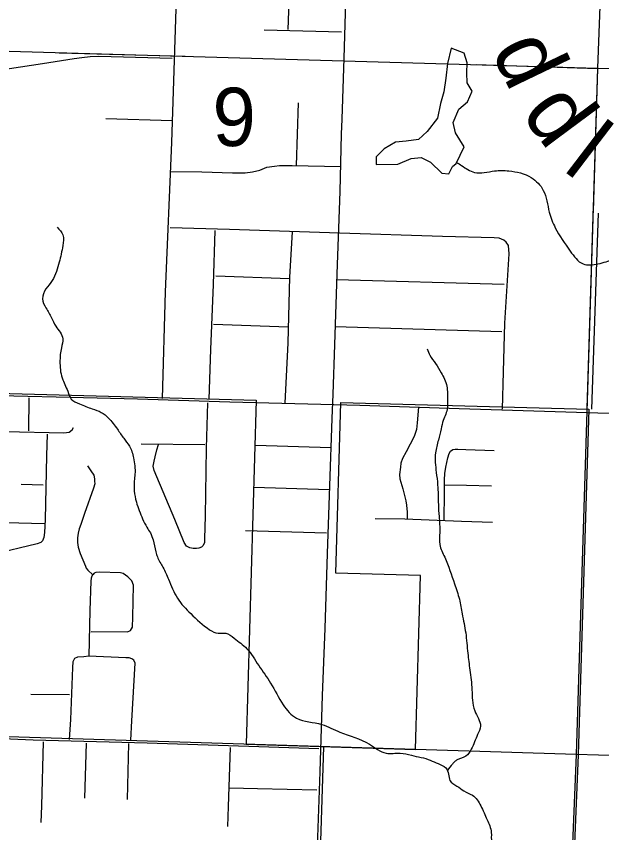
# Model space of a CAD drawing. Extents: x 1219626 to 1426462, y 456797 to 752399.
# Drawn here: x 1322578 to 1327096, y 647254 to 653553 of the extents above; entities that cross this region are included whole.
import ezdxf

# ---------------------------------------------------------------- set-up
doc = ezdxf.new("R2010")
doc.units = 0
for name, color, linetype in [('Cities Incorporated Area', 7, 'Continuous'), ('City Streets', 7, 'Continuous'), ('Connecting Roads', 7, 'Continuous'), ('Lakes and Ponds', 7, 'Continuous'), ('Local Roads Improved', 7, 'Continuous'), ('Local Roads Paved', 7, 'Continuous'), ('Masks', 7, 'Continuous'), ('Narrow River Creek and Branch and Slough', 7, 'Continuous'), ('Narrow River Creek and Branch and Slough Text', 7, 'Continuous'), ('Section Lines', 7, 'Continuous'), ('Section Numbers', 7, 'Continuous')]:
    doc.layers.add(name, color=color, linetype=linetype)

msp = doc.modelspace()

# ---------------------------------------------------------------- linework, layer by layer
at = {"layer": 'Cities Incorporated Area'}
for p, q in [((1319885.5, 650716.4), (1324429, 650591.4)), ((1324429, 650591.4), (1324350.8, 647936.5)), ((1325044.4, 649257.1), (1325083.1, 650573.4)), ((1325083.1, 650573.4), (1326997.1, 650520.9)), ((1326997.1, 650520.9), (1326914.4, 647855.9)), ((1325698.5, 649237.8), (1325044.4, 649257.1)), ((1325659.3, 647895.3), (1325698.5, 649237.8)), ((1324350.8, 647936.5), (1325659.3, 647895.3)), ((1326914.4, 647855.9), (1326816, 645432.8))]:
    msp.add_line(p, q, dxfattribs=at)
at = {"layer": 'City Streets'}
for p, q in [((1322674.9, 650609.4), (1322671.5, 650355.6)), ((1323542.1, 650254.1), (1324034.2, 650249.8)), ((1322785.9, 649934.9), (1322616.4, 649940.1)), ((1322989.8, 648316.6), (1322691.2, 648320)), ((1323116.3, 647944.1), (1323105.1, 647519.9)), ((1323444, 647941.5), (1323433.7, 647510.5))]:
    msp.add_line(p, q, dxfattribs=at)
for points in [[(1324054, 650570.7), (1324042.8, 650220.5), (1324036, 649695.7), (1324030.8, 649523.7), (1324030.8, 649494.4), (1324021.3, 649471.2), (1324007.6, 649457.4), (1323986.9, 649449.7), (1323968, 649447.1), (1323942.2, 649446.2), (1323916.4, 649451.4), (1323891.4, 649465.2), (1323873.4, 649494.4), (1323801.9, 649669.9), (1323641.1, 650047.6), (1323634.2, 650082), (1323641.1, 650119.9), (1323650.5, 650154.3), (1323663.4, 650207.6), (1323675.5, 650248.1)], [(1322408.2, 650456.3), (1322422, 650395.2), (1322428, 650374.5), (1322435.7, 650361.6), (1322449.5, 650354.7), (1322488.2, 650349.6), (1322944.2, 650339.3), (1322987.2, 650345.3), (1323008.7, 650361.6), (1323019.9, 650379.7)], [(1322816.9, 650328.9), (1322810, 650161.2), (1322799.6, 649670.8), (1322795.3, 649569.3), (1322791, 649530.5), (1322779, 649507.3), (1322767.8, 649492.7), (1322738.6, 649483.2), (1322395.3, 649400.6), (1322364.3, 649399.8), (1322237, 649402.3), (1322194, 649404.1), (1322177.6, 649408.4), (1322161.3, 649419.6), (1322150.1, 649436.8), (1322144.9, 649451.4), (1322144.9, 649484.9), (1322150.9, 649606.2), (1322156.1, 649626), (1322175.9, 649646.7), (1322202.6, 649655.3), (1322694.7, 649641.5), (1322796.2, 649639.8)], [(1323126.6, 650083.7), (1323154.1, 650045.9), (1323175.6, 650012.3), (1323182.5, 649984.8), (1323182.5, 649966.7), (1323183.4, 649946.1), (1323173, 649912.5), (1323105.1, 649716.4), (1323075, 649631.2), (1323063.8, 649597.6), (1323054.3, 649564.1), (1323050.9, 649528), (1323050.9, 649494.4), (1323056, 649458.3), (1323069.8, 649409.2), (1323111.1, 649310.3), (1323118, 649294.8), (1323130, 649281), (1323168.9, 649243.9)], [(1323166.9, 649245.8), (1323156.7, 649219.1), (1323154.1, 649195.9), (1323146.4, 648967.9), (1323136.9, 648616), (1323099.9, 648611.7), (1323050, 648608.3), (1323025.9, 648598.8), (1323013.9, 648573), (1323011.3, 648529.1), (1322995.8, 648126.5), (1322987.2, 647973.3)], [(1323156.7, 648805.3), (1323437.2, 648802.7), (1323460.4, 648813.9), (1323474.2, 648840.5), (1323477.6, 648918), (1323483.6, 649164.9), (1323469, 649198.4), (1323438, 649227.7), (1323402.7, 649254.4), (1323382.1, 649259.5), (1323219.5, 649263.8), (1323192, 649262.1), (1323178.2, 649257.8), (1323168.9, 649243.9)], [(1323461.2, 647969), (1323470.7, 648116.1), (1323494.8, 648562.7), (1323486.2, 648585.9), (1323470.7, 648596.2), (1323449.2, 648603.1), (1323423.4, 648603.9), (1323136.9, 648616)], [(1324913.5, 647901.9), (1324448.9, 647917.4), (1323586.9, 647944.1), (1322709.3, 647969), (1322179.3, 647990.5), (1322077.8, 647988.8), (1322003, 647983.6), (1321911.8, 647973.3), (1321783.6, 647956.1), (1321736.3, 647952.7), (1321724.2, 647950.9), (1321651.9, 647950.9)], [(1322784.2, 647955.3), (1322772.1, 647461.4), (1322767.8, 647333.2)], [(1324228.7, 647912.2), (1324212.3, 647456.3), (1324208.9, 647301.4)], [(1324898, 647582.7), (1324440.3, 647593), (1324223.5, 647598.2)]]:
    msp.add_lwpolyline(points, dxfattribs=at)
at = {"layer": 'Connecting Roads'}
msp.add_line((1324948.8, 647917.8), (1324913, 646749.8), dxfattribs=at)
at = {"layer": 'Lakes and Ponds'}
msp.add_lwpolyline([(1325972.6, 652417.2), (1326035.6, 652547.1), (1325968.6, 652655.3), (1325950.7, 652732.7), (1325994.4, 652835.9), (1326059.9, 652893.4), (1326095.6, 652974.8), (1326057.9, 653040.3), (1326053.9, 653117.7), (1326057.9, 653195), (1326034.1, 653268.5), (1325934.9, 653308.2), (1325907.1, 653190), (1325894.3, 653076.9), (1325878.9, 652971.4), (1325853.2, 652881.4), (1325827.5, 652768.3), (1325748.3, 652665.2), (1325682.9, 652603.7), (1325587.6, 652589.8), (1325504.3, 652581.9), (1325417, 652530.3), (1325355.5, 652468.8), (1325354.6, 652410.9), (1325523.4, 652411.4), (1325624.6, 652455.1), (1325701.5, 652464.9), (1325774.1, 652427.1), (1325863.4, 652344), (1325917.4, 652338.9), (1325944.8, 652393.4)], close=True, dxfattribs=at)
at = {"layer": 'Local Roads Improved'}
msp.add_line((1327020.7, 650521.4), (1327070.2, 652033.6), dxfattribs=at)
at = {"layer": 'Local Roads Paved'}
for p, q in [((1325088.7, 653431), (1324490.6, 653447)), ((1324739.5, 652401), (1324755.4, 652886.8)), ((1323268.1, 652764.6), (1323781.1, 652748.5)), ((1324686.4, 651528), (1324118.7, 651547.9)), ((1325050.2, 651523.6), (1326343.5, 651485.8)), ((1324101, 651178.7), (1324676.6, 651157.9)), ((1326325.8, 651118.4), (1325037.8, 651158)), ((1324423.1, 650245.1), (1325005.6, 650227.1)), ((1324993, 649900.1), (1324412.5, 649918.6)), ((1324972.9, 649565.8), (1324346.5, 649583))]:
    msp.add_line(p, q, dxfattribs=at)
for points in [[(1323888.4, 656073.7), (1323850.1, 654909.3), (1323809.2, 653610.1), (1323775.5, 652578.9), (1323725.8, 651427), (1323702.7, 650603.4)], [(1324675.4, 653450.3), (1324703.8, 654233.1), (1324733.9, 655228.8), (1324757, 655853.5)], [(1325186.5, 655838.4), (1325172.3, 655396.5), (1325160.8, 655004.2), (1325141.3, 654352), (1325121.7, 653753.8), (1325104.9, 653229.4), (1325100.5, 653073.2), (1325089.8, 652760.8), (1325084.5, 652643.7), (1325074.7, 652201.7), (1325051.6, 651567.2), (1325033, 651017.9), (1325020.6, 650637.2), (1325014.4, 650449.9), (1324994, 649930.8), (1324977.1, 649407.2), (1324958.5, 648828.6), (1324939.8, 648313), (1324921.2, 647722.8), (1324903.4, 647218.8), (1324883, 646596.7), (1324865.3, 646059.8), (1324861.7, 645840.6)], [(1323780.9, 653228.3), (1323309.4, 653239.5), (1323215.6, 653242.1), (1323146.8, 653240.3), (1323084, 653233.5), (1323025.5, 653224.9), (1322780.3, 653187), (1322438.7, 653136.2), (1322331.2, 653123.3), (1322252.9, 653122.5), (1322208.2, 653127.6), (1322127.3, 653146.6), (1322058.5, 653176.7), (1321877.8, 653273), (1321830.5, 653284.2), (1321764.2, 653286.8), (1321294.3, 653295.2)], [(1323765.9, 652355.6), (1324009.6, 652353.7), (1324247.4, 652345.7), (1324343.2, 652344.8), (1324400, 652352.8), (1324457.7, 652366.1), (1324511, 652390.1), (1324569.5, 652398.1), (1324608.6, 652401.6), (1324708, 652401.6), (1325079, 652394.2)], [(1326330.2, 650522.9), (1326337.3, 650809.5), (1326349.7, 651186.7), (1326380.8, 651721.8), (1326377.3, 651785.7), (1326359.5, 651811.5), (1326340.9, 651826.6), (1326305.4, 651840.8), (1326266.3, 651845.2), (1325867, 651855), (1325072.7, 651879.8), (1324224.3, 651907.3), (1323766.4, 651921.5)], [(1324065.5, 650598.3), (1324079.7, 650983.5), (1324099.2, 651483.1), (1324111.6, 651900.2)], [(1324707.9, 651891.6), (1324686.7, 651539.9), (1324673.4, 651035), (1324650.5, 650567.6)], [(1320027.6, 650735.9), (1320226.4, 650724.4), (1320356.9, 650712.8), (1320497.1, 650697.7), (1320595.6, 650690.6), (1320673.7, 650685.3), (1321304.7, 650664.9), (1322029.7, 650642.7), (1322557.7, 650625.9), (1322994.3, 650613.4), (1323512.6, 650602.8), (1324227, 650578.8), (1325229.8, 650552.2), (1325996.5, 650527.3), (1327066.8, 650493.6), (1328109.5, 650466.1), (1328291.4, 650464.1)], [(1325682.2, 650537.5), (1325672.3, 650416.7), (1325667.2, 650365.9), (1325649.1, 650310.9), (1325588, 650192.6), (1325558.3, 650141), (1325546.7, 650105.2), (1325542, 650073.4), (1325536.4, 650017.1), (1325539, 649983.5), (1325560.1, 649907.8), (1325584.1, 649815.3), (1325589.7, 649782.2), (1325594.9, 649728.4), (1325593.9, 649673.9)], [(1325879.6, 649662.2), (1325882.3, 649878.1), (1325883.1, 649977.9), (1325884.4, 650024.4), (1325892.6, 650073.8), (1325909.8, 650145.3), (1325918.8, 650180.1), (1325929.1, 650199), (1325948.1, 650210.6), (1325966.1, 650212.4), (1325985.9, 650212.8), (1326047, 650210.6), (1326266.8, 650202.9)], [(1326245.3, 649928), (1326053, 649934), (1325882.7, 649935)], [(1325347.1, 649678.9), (1325576.8, 649674.6), (1326014.7, 649656.6), (1326253.5, 649651)]]:
    msp.add_lwpolyline(points, dxfattribs=at)
at = {"layer": 'Masks'}
for p, q in [((1322908.2, 653272.8), (1323880.8, 653245.1)), ((1326126.4, 653181.1), (1327063.8, 653151.9)), ((1327063.8, 653151.9), (1327029.6, 652049.9)), ((1327031, 652094.5), (1326982.3, 650528.4))]:
    msp.add_line(p, q, dxfattribs=at)
at = {"layer": 'Narrow River Creek and Branch and Slough'}
for points in [[(1325976.9, 652426.2), (1326015.1, 652401.2), (1326113.4, 652349.1), (1326269.5, 652360.7), (1326379.4, 652360.7), (1326552.9, 652308.6), (1326645.4, 652210.3), (1326691.6, 652042.5), (1326737.9, 651921), (1326853.6, 651741.6), (1326951.9, 651643.3), (1327067.5, 651643.3), (1327188.9, 651678), (1327397.1, 651730.1), (1327559, 651753.2), (1327744.1, 651747.4), (1327900.2, 651741.6), (1328021.6, 651718.5), (1328062.1, 651654.8), (1328137.3, 651597), (1328252.9, 651539.1), (1328322.3, 651458.1), (1328397.5, 651348.2), (1328466.9, 651273), (1328524.7, 651238.3), (1328599.9, 651203.6), (1328675.1, 651145.7), (1328761.8, 651082.1), (1328854.3, 650983.7), (1328946.8, 650896.9), (1329062.5, 650827.5), (1329253.3, 650769.6), (1329467.3, 650734.9), (1329705.5, 650696.9), (1329907.9, 650673.8), (1330087.2, 650604.4), (1330260.7, 650506), (1330335.8, 650419.2), (1330434.1, 650361.4), (1330520.9, 650315.1), (1330642.3, 650199.4), (1330700.1, 650129.9), (1330752.2, 650020), (1330821.6, 649875.4), (1330862, 649771.2), (1330914.1, 649690.2), (1330960.3, 649615), (1331070.2, 649562.9), (1331128, 649510.9), (1331226.3, 649406.7), (1331284.2, 649308.4), (1331376.7, 649204.2), (1331469.2, 649105.9), (1331561.7, 649030.6), (1331631.1, 648961.2), (1331671.6, 648851.3), (1331816.2, 648742.4), (1331897.1, 648667.2), (1331960.7, 648626.7), (1332059, 648586.2), (1332174.7, 648557.2), (1332325, 648551.5), (1332440.7, 648539.9), (1332562.1, 648470.5), (1332643.1, 648401), (1332718.2, 648314.2), (1332770.3, 648233.2), (1332784.7, 648199.2)], [(1322893.5, 651925.7), (1322936.8, 651866.2), (1322936.8, 651785), (1322909.7, 651655.2), (1322888.1, 651584.9), (1322855.7, 651514.5), (1322807, 651449.6), (1322780, 651373.9), (1322807, 651303.6), (1322850.3, 651227.8), (1322882.7, 651162.9), (1322936.8, 651065.5), (1322926, 650995.2), (1322915.2, 650892.4), (1322931.4, 650762.6), (1322974.6, 650659.8), (1323001.7, 650600.3), (1323066.6, 650562.4), (1323163.9, 650524.5), (1323234.2, 650497.5), (1323288.2, 650454.2), (1323358.5, 650367.7), (1323407.2, 650297.3), (1323450.4, 650237.8), (1323482.9, 650145.8), (1323493.7, 650021.4), (1323488.3, 649967.3), (1323488.3, 649891.6), (1323504.5, 649805), (1323553.2, 649675.2), (1323585.6, 649610.3), (1323612.7, 649567), (1323634.3, 649512.9), (1323655.9, 649420.9), (1323666.7, 649383), (1323710, 649301.9), (1323753.2, 649209.9), (1323821.4, 649063.2), (1323924.1, 648944.2), (1324070.1, 648819.8), (1324135, 648792.7), (1324194.4, 648792.7), (1324259.3, 648754.8), (1324356.6, 648673.7), (1324448.6, 648543.9), (1324540.5, 648408.6), (1324637.8, 648240.9), (1324740.5, 648138.1), (1324935.2, 648089.4), (1325075.8, 648029.9), (1325302.9, 647937.9), (1325432.6, 647867.6), (1325540.8, 647867.6), (1325627.3, 647851.4), (1325773.3, 647813.5), (1325832.7, 647787), (1325892.2, 647754.5), (1325913.8, 647705.9), (1325924.7, 647657.2), (1325978.7, 647613.9), (1326032.8, 647576), (1326097.7, 647543.6), (1326162.6, 647462.4), (1326211.2, 647354.2), (1326243.7, 647256.8), (1326249.1, 647181.1), (1326297.7, 647116.2), (1326330.2, 647051.3), (1326351.8, 646899.8), (1326373.4, 646791.6), (1326400.5, 646661.7), (1326416.7, 646580.6), (1326454.5, 646521.1), (1326487, 646461.6), (1326524.8, 646450.8), (1326578.9, 646429.1), (1326611.3, 646353.4), (1326616.7, 646272.2), (1326608.6, 646168.6), (1326587, 646109.1), (1326554.6, 646044.2), (1326570.8, 645963.1), (1326565.4, 645919.8), (1326532.9, 645822.4), (1326522.1, 645762.9), (1326532.9, 645703.4), (1326560, 645660.1), (1326576.2, 645622.2), (1326592.4, 645579), (1326624.9, 645551.9), (1326678.9, 645514.1)], [(1325748.9, 650986.7), (1325770.6, 650938), (1325813.8, 650873.1), (1325857.1, 650802.8), (1325900.3, 650700), (1325905.7, 650586.4), (1325905.7, 650532.3), (1325873.3, 650434.9), (1325857.1, 650370), (1325835.4, 650283.4), (1325813.8, 650186), (1325819.2, 650034.6), (1325830, 649937.2), (1325835.4, 649785.7), (1325840.9, 649693.7), (1325846.3, 649569.3), (1325846.3, 649477.3), (1325884.1, 649380), (1325959.8, 649174.4), (1325997.7, 649055.4), (1326019.3, 648941.8), (1326046.3, 648795.7), (1326062.5, 648638.8), (1326078.8, 648509), (1326095, 648357.5), (1326116.6, 648195.2), (1326159.9, 648076.2), (1326138.2, 648011.3), (1326089.6, 647897.7), (1326046.3, 647843.6), (1325981.4, 647816.5), (1325959.8, 647800.3), (1325943.6, 647784), (1325905.7, 647733.4)], [(1321090.4, 648474.5), (1321085.3, 648397.9), (1321064.9, 648321.3), (1321024.1, 648270.2), (1320983.2, 648244.6), (1320932.2, 648188.5), (1320886.2, 648122.1), (1320881.1, 648060.8), (1320922, 647963.7), (1320983.2, 647825.8), (1321059.8, 647677.7), (1321095.5, 647596), (1321131.3, 647498.9), (1321182.3, 647473.4), (1321253.8, 647493.8), (1321361, 647529.6), (1321452.9, 647544.9), (1321590.7, 647555.1), (1321728.5, 647555.1), (1321825.5, 647544.9), (1321866.3, 647514.3), (1321942.9, 647534.7), (1321999.1, 647524.5), (1322055.2, 647453), (1322085.8, 647422.3), (1322101.2, 647381.5), (1322039.9, 647269.1), (1321907.2, 647172.1), (1321835.7, 647054.6), (1321815.3, 646937.1), (1321835.7, 646840.1), (1321891.9, 646773.7), (1321978.6, 646753.2), (1322116.5, 646712.4), (1322290, 646697.1), (1322473.8, 646737.9), (1322530, 646758.3), (1322560.6, 646804.3), (1322616.7, 646845.2), (1322734.1, 646906.5), (1322856.7, 646962.6), (1322938.3, 646983.1), (1322999.6, 646957.5), (1323066, 646855.4), (1323096.6, 646763.5), (1323106.8, 646656.2), (1323122.1, 646600), (1323152.7, 646523.4), (1323188.5, 646472.3), (1323224.2, 646411), (1323270.1, 646319.1), (1323290.6, 646262.9), (1323270.1, 646191.4), (1323249.7, 646114.8), (1323259.2, 646075.9)]]:
    msp.add_spline(points, degree=3, dxfattribs=at)
at = {"layer": 'Section Lines'}
for p, q in [((1327269.1, 658458.8), (1327063.9, 653154.4)), ((1321844.6, 653303.1), (1327063.9, 653154.4)), ((1327063.9, 653154.4), (1326899.4, 647856.3)), ((1327063.9, 653154.4), (1332352.2, 652988.6)), ((1326899.4, 647856.3), (1321651, 648021.5)), ((1326899.4, 647856.3), (1326684.8, 642567.4)), ((1332165.2, 647726.9), (1326899.4, 647856.3))]:
    msp.add_line(p, q, dxfattribs=at)

# ---------------------------------------------------------------- texts
at = {"layer": 'Narrow River Creek and Branch and Slough Text'}
for s, rotation, p in [('d', 295.64982, (1326238.6, 653289.5)), ('d', 306.55944, (1326467, 652802.9)), ('l', 322.63683, (1326787.9, 652370.2))]:
    msp.add_text(s, height=500, rotation=rotation, dxfattribs=at).set_placement(p)
at = {"layer": 'Section Numbers'}
msp.add_text('9', height=450, rotation=359.99983, dxfattribs=at).set_placement((1324091.9, 652552.3))

doc.saveas('drawing.dxf')
